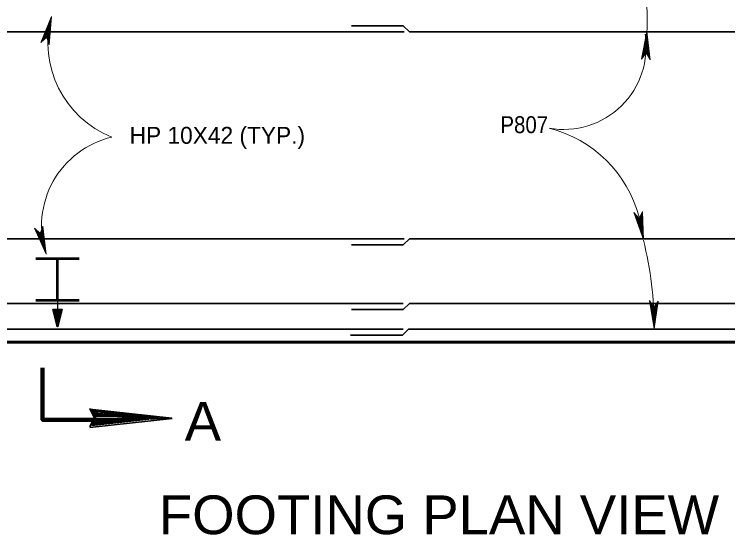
# Model space of a CAD drawing. Extents: x 144 to 252, y 360 to 425.
# Drawn here: x 160.77 to 174.56, y 388.73 to 398.8 of the extents above; entities that cross this region are included whole.
import ezdxf
from ezdxf.enums import TextEntityAlignment as Align

# ---------------------------------------------------------------- set-up
doc = ezdxf.new("R2010")
doc.units = 0
doc.header["$LTSCALE"] = 0.13
for name, color, linetype, lineweight in [('1', 7, 'Continuous', 40), ('10', 7, 'Continuous', 35), ('14', 7, 'Continuous', 13), ('16', 7, 'Continuous', 13), ('3', 7, 'Continuous', 13), ('9', 7, 'Continuous', 25)]:
    doc.layers.add(name, color=color, linetype=linetype, lineweight=lineweight)

msp = doc.modelspace()

# ---------------------------------------------------------------- linework, layer by layer
at = {"layer": '1', "lineweight": 35}
for p, q in [((156.5478, 398.4595), (168.3034, 398.4595)), ((168.4074, 398.4595), (180.0478, 398.4595)), ((156.5478, 394.4595), (168.3034, 394.4595)), ((168.4074, 394.4595), (180.0478, 394.4595)), ((156.5478, 393.2095), (168.2861, 393.2095)), ((168.4074, 393.2095), (180.0478, 393.2095)), ((156.5478, 392.7095), (168.2861, 392.7095)), ((168.3901, 392.7095), (180.0478, 392.7095)), ((162.2276, 391.1635), (163.8176, 390.9865)), ((162.2636, 391.1215), (163.4456, 390.9925)), ((162.2666, 391.1485), (163.4516, 391.0195)), ((162.2666, 391.1425), (163.4516, 391.0165)), ((162.2666, 391.1365), (163.4456, 391.0045)), ((162.2696, 391.1545), (163.4516, 391.0255)), ((163.8206, 390.9835), (162.2306, 390.8065)), ((162.2306, 390.9805), (163.8206, 390.9805)), ((162.2606, 390.8995), (163.3646, 391.0195)), ((162.2636, 390.8815), (163.3646, 391.0015)), ((162.2666, 390.8635), (163.3706, 390.9835)), ((162.2696, 390.8485), (163.3736, 390.9685))]:
    msp.add_line(p, q, dxfattribs=at)
at = {"layer": '1', "lineweight": 53}
for p, q in [((161.1876, 394.0775), (162.0272, 394.0775)), ((161.6073, 393.2692), (161.6073, 394.0775)), ((161.1875, 393.2692), (162.0271, 393.2692))]:
    msp.add_line(p, q, dxfattribs=at)
at = {"layer": '1', "lineweight": 25}
msp.add_line((161.6073, 393.2692), (161.6073, 392.7692), dxfattribs=at)
at = {"layer": '1', "lineweight": 60}
for p, q in [((180.2978, 392.4595), (156.2978, 392.4595)), ((156.2978, 392.4595), (180.2978, 392.4595))]:
    msp.add_line(p, q, dxfattribs=at)
msp.add_lwpolyline([(156.2978, 392.4595), (180.2978, 392.4595), (180.2978, 397.8819)], dxfattribs=at)
at = {"layer": '1', "lineweight": 35}
for points in [[(162.2336, 390.8215), (162.3176, 391.0015), (162.2336, 391.1755)], [(162.3416, 391.0195), (163.0496, 391.0285), (163.0466, 391.0105), (162.9086, 391.0195), (162.3416, 391.0285), (162.7976, 391.0435), (162.3206, 391.0525), (162.6566, 391.0645), (162.3086, 391.0825), (162.8516, 391.0405), (163.5596, 391.0105), (163.4126, 390.9715), (163.6076, 390.9895), (162.3416, 390.9835), (162.7106, 390.9595), (162.3206, 390.9595), (163.1306, 391.0165), (162.3146, 390.9265), (162.3446, 391.0165), (162.2786, 391.1275), (162.3146, 391.1035), (162.3446, 391.0405), (162.3866, 391.0585), (162.3596, 391.1095), (162.3356, 390.9955), (162.3026, 390.9265), (162.2696, 390.8485)]]:
    msp.add_lwpolyline(points, dxfattribs=at)
at = {"layer": '10'}
for p, q in [((161.6038, 392.9078), (161.6115, 393.0913)), ((161.6077, 393.0913), (161.6077, 392.7561)), ((161.6178, 393.0913), (161.6101, 392.9077)), ((161.6163, 392.9075), (161.6241, 393.0913)), ((161.6227, 392.9074), (161.6303, 393.0913)), ((161.6555, 393.0913), (161.6482, 392.9187))]:
    msp.add_line(p, q, dxfattribs=at)
for points in [[(161.5242, 393.0913), (161.6912, 393.0913), (161.6078, 392.7561)], [(161.5242, 393.0913), (161.6078, 392.7561), (161.5242, 393.0913)]]:
    msp.add_lwpolyline(points, dxfattribs=at)
msp.add_lwpolyline([(161.6078, 392.7561), (161.5242, 393.0913), (161.6912, 393.0913), (161.5242, 393.0913)], close=True, dxfattribs=at)
at = {"layer": '16', "lineweight": 106}
msp.add_lwpolyline([(161.3189, 391.9598), (161.3189, 390.9598), (162.3189, 390.9598)], dxfattribs=at)
at = {"layer": '16'}
for centre, radius, start, end in [((165.653, 398.6917), 7.3474, 358.12487, 8.06122), ((163.388, 398.2493), 1.9649, 164.92487, 248.20523), ((171.3847, 398.1691), 1.5968, 260.00291, 8.92656), ((170.5186, 394.2613), 2.4084, 15.03373, 75.84704), ((163.0645, 394.7075), 1.7647, 103.30356, 198.14467), ((166.5087, 392.7914), 6.6256, 359.34281, 14.34295)]:
    msp.add_arc(centre, radius, start, end, dxfattribs=at)
at = {"layer": '3'}
for p, q in [((161.4907, 398.7603), (161.2877, 398.2545)), ((161.4869, 398.7464), (161.2907, 398.2572)), ((161.4846, 398.7358), (161.2936, 398.2598)), ((161.4815, 398.7217), (161.2977, 398.2633)), ((161.4787, 398.7092), (161.301, 398.2664)), ((161.4762, 398.6982), (161.3041, 398.2692)), ((161.4732, 398.6842), (161.3082, 398.2727)), ((161.4704, 398.6717), (161.3116, 398.2757)), ((161.4675, 398.6583), (161.3153, 398.2791)), ((161.4012, 398.3547), (161.4907, 398.7603)), ((161.436, 398.2462), (161.4675, 398.6583)), ((161.4375, 398.2413), (161.4704, 398.6717)), ((161.439, 398.2368), (161.4732, 398.6842)), ((161.4406, 398.2317), (161.4762, 398.6982)), ((161.4419, 398.2278), (161.4787, 398.7092)), ((161.4419, 398.2278), (161.4787, 398.7092)), ((161.4434, 398.2233), (161.4815, 398.7217)), ((161.445, 398.2182), (161.4846, 398.7358)), ((161.4462, 398.2143), (161.4869, 398.7464)), ((161.4483, 398.2077), (161.4907, 398.7603)), ((161.4645, 398.6447), (161.3192, 398.2824)), ((161.4617, 398.6318), (161.3227, 398.2856)), ((161.4587, 398.6182), (161.3266, 398.2889)), ((161.4559, 398.6059), (161.33, 398.292)), ((161.4534, 398.5948), (161.3332, 398.2948)), ((161.4501, 398.5795), (161.3374, 398.2986)), ((161.4471, 398.566), (161.3413, 398.3019)), ((161.4427, 398.5485), (161.3452, 398.3054)), ((161.4398, 398.5349), (161.349, 398.3088)), ((161.4369, 398.5221), (161.3526, 398.312)), ((161.4354, 398.5131), (161.3561, 398.3151)), ((161.4191, 398.2987), (161.4354, 398.5131)), ((161.4196, 398.2971), (161.4369, 398.5221)), ((161.4212, 398.2924), (161.4398, 398.5349)), ((161.4227, 398.2875), (161.4427, 398.5485)), ((161.4239, 398.284), (161.4439, 398.5467)), ((161.4253, 398.2797), (161.4471, 398.566)), ((161.4269, 398.2747), (161.4501, 398.5795)), ((161.4286, 398.2692), (161.4534, 398.5948)), ((161.4299, 398.2651), (161.4559, 398.6059)), ((161.4313, 398.2607), (161.4587, 398.6182)), ((161.4329, 398.2557), (161.4617, 398.6318)), ((161.4344, 398.2511), (161.4645, 398.6447)), ((161.4328, 398.5014), (161.3593, 398.318)), ((161.4298, 398.4878), (161.3632, 398.3213)), ((161.4265, 398.4726), (161.3673, 398.3252)), ((161.4237, 398.4602), (161.3708, 398.3282)), ((161.4209, 398.4473), (161.3744, 398.3314)), ((161.4183, 398.4356), (161.3778, 398.3343)), ((161.4152, 398.4215), (161.3817, 398.3378)), ((161.4123, 398.4079), (161.3855, 398.3413)), ((161.4095, 398.3956), (161.3889, 398.3442)), ((161.4067, 398.3827), (161.3926, 398.3474)), ((161.4055, 398.3413), (161.4095, 398.3956)), ((161.4068, 398.3368), (161.4123, 398.4079)), ((161.4084, 398.332), (161.4152, 398.4215)), ((161.41, 398.3268), (161.4183, 398.4356)), ((161.4114, 398.3227), (161.4209, 398.4473)), ((161.4129, 398.3179), (161.4237, 398.4602)), ((161.4144, 398.3134), (161.4265, 398.4726)), ((161.4161, 398.3079), (161.4298, 398.4878)), ((161.4177, 398.3031), (161.4328, 398.5014)), ((172.9952, 398.4685), (172.8906, 397.9337)), ((172.994, 398.4541), (172.893, 397.9367)), ((172.9938, 398.4432), (172.8954, 397.9399)), ((172.9933, 398.4289), (172.8988, 397.9442)), ((172.9931, 398.4161), (172.9015, 397.9477)), ((172.9927, 398.4047), (172.904, 397.951)), ((172.9923, 398.3903), (172.9073, 397.9552)), ((172.9918, 398.3776), (172.9102, 397.9588)), ((172.9833, 398.0532), (172.9952, 398.4685)), ((173.0402, 397.9487), (172.9918, 398.3776)), ((173.0426, 397.9446), (172.9923, 398.3903)), ((173.0451, 397.9399), (172.9927, 398.4047)), ((173.0472, 397.9362), (172.9931, 398.4161)), ((173.0472, 397.9362), (172.9931, 398.4161)), ((173.0495, 397.932), (172.9933, 398.4289)), ((173.0519, 397.9274), (172.9938, 398.4432)), ((173.0539, 397.9238), (172.994, 398.4541)), ((173.0572, 397.9178), (172.9952, 398.4685)), ((161.2877, 398.2545), (161.4011, 398.3549)), ((161.4042, 398.3715), (161.3957, 398.3502)), ((161.402, 398.3616), (161.3985, 398.3527)), ((161.4011, 398.3549), (161.4483, 398.2077)), ((161.4026, 398.3501), (161.4042, 398.3715)), ((161.4036, 398.3472), (161.4055, 398.3724)), ((172.9915, 398.3639), (172.9132, 397.9628)), ((172.9912, 398.35), (172.9163, 397.9668)), ((172.9907, 398.3368), (172.9192, 397.9707)), ((172.9903, 398.3228), (172.9224, 397.9747)), ((172.9899, 398.3103), (172.9252, 397.9783)), ((172.9897, 398.299), (172.9278, 397.9817)), ((172.9892, 398.2833), (172.9312, 397.9862)), ((172.9888, 398.2694), (172.9343, 397.9902)), ((172.9878, 398.2514), (172.9375, 397.9943)), ((172.9874, 398.2375), (172.9406, 397.9984)), ((173.0146, 397.9958), (172.9874, 398.2375)), ((173.0171, 397.9913), (172.9878, 398.2514)), ((173.021, 397.984), (172.9888, 398.2694)), ((173.0236, 397.9796), (172.9892, 398.2833)), ((173.0188, 397.9882), (172.9893, 398.2498)), ((173.0263, 397.9744), (172.9897, 398.299)), ((173.0283, 397.9707), (172.9899, 398.3103)), ((173.0305, 397.9667), (172.9903, 398.3228)), ((173.0331, 397.9621), (172.9907, 398.3368)), ((173.0354, 397.9577), (172.9912, 398.35)), ((173.0379, 397.9532), (172.9915, 398.3639)), ((172.9871, 398.2243), (172.9436, 398.0022)), ((172.9872, 398.2152), (172.9464, 398.0058)), ((172.9869, 398.2032), (172.9491, 398.0093)), ((172.9864, 398.1894), (172.9522, 398.0134)), ((172.9861, 398.1737), (172.9557, 398.0179)), ((172.9857, 398.1612), (172.9584, 398.0215)), ((172.9853, 398.148), (172.9615, 398.0254)), ((172.985, 398.1359), (172.9642, 398.0288)), ((172.9846, 398.1215), (172.9673, 398.0331)), ((172.9842, 398.1077), (172.9704, 398.0371)), ((172.9922, 398.0368), (172.9842, 398.1077)), ((172.9947, 398.0323), (172.9846, 398.1215)), ((172.9973, 398.0276), (172.985, 398.1359)), ((172.9994, 398.0237), (172.9853, 398.148)), ((173.0017, 398.0193), (172.9857, 398.1612)), ((173.0041, 398.0152), (172.9861, 398.1737)), ((173.0067, 398.0102), (172.9864, 398.1894)), ((173.0093, 398.0057), (172.9869, 398.2032)), ((173.0122, 398.0001), (172.9871, 398.2243)), ((173.0114, 398.0016), (172.9872, 398.2152)), ((172.8906, 397.9337), (172.9832, 398.0535)), ((172.9837, 398.095), (172.9733, 398.0407)), ((172.9834, 398.0817), (172.9762, 398.0445)), ((172.9832, 398.0703), (172.9787, 398.0479)), ((172.9828, 398.0602), (172.9811, 398.0508)), ((172.9856, 398.049), (172.9832, 398.0703)), ((172.9832, 398.0535), (173.0572, 397.9178)), ((172.99, 398.0409), (172.9837, 398.095)), ((172.9872, 398.0463), (172.9843, 398.0714)), ((172.7463, 394.9668), (172.9281, 394.4433)), ((172.8486, 394.8508), (172.7463, 394.9668)), ((172.751, 394.9617), (172.926, 394.4576)), ((172.7536, 394.9587), (172.9239, 394.4682)), ((172.7572, 394.9547), (172.9212, 394.4823)), ((172.7603, 394.9511), (172.9187, 394.4948)), ((172.7603, 394.9511), (172.9187, 394.4948)), ((172.7631, 394.9479), (172.9165, 394.506)), ((172.7666, 394.944), (172.9137, 394.5202)), ((172.7697, 394.9404), (172.9113, 394.5327)), ((172.773, 394.9365), (172.9087, 394.5462)), ((172.7765, 394.9327), (172.906, 394.5598)), ((172.7798, 394.9291), (172.9035, 394.5727)), ((172.9124, 394.9881), (172.8486, 394.8508)), ((172.8932, 394.6252), (172.8844, 394.9278)), ((172.8962, 394.6099), (172.8868, 394.933)), ((172.8983, 394.5987), (172.8886, 394.9368)), ((172.9007, 394.5864), (172.8905, 394.941)), ((172.9035, 394.5727), (172.8926, 394.9456)), ((172.906, 394.5598), (172.8947, 394.95)), ((172.9087, 394.5462), (172.8968, 394.9546)), ((172.9113, 394.5327), (172.8989, 394.9592)), ((172.9137, 394.5202), (172.9008, 394.9633)), ((172.9165, 394.506), (172.9032, 394.9682)), ((172.9187, 394.4948), (172.9048, 394.9718)), ((172.9212, 394.4823), (172.9067, 394.9761)), ((172.9239, 394.4682), (172.9091, 394.9808)), ((172.926, 394.4576), (172.9108, 394.9844)), ((172.9281, 394.4433), (172.9124, 394.9881)), ((172.7832, 394.9251), (172.9007, 394.5864)), ((172.7862, 394.9216), (172.8983, 394.5987)), ((172.7891, 394.9183), (172.8962, 394.6099)), ((172.7928, 394.914), (172.8932, 394.6252)), ((172.7963, 394.9102), (172.8905, 394.6388)), ((172.7993, 394.9067), (172.8857, 394.6579)), ((172.8018, 394.904), (172.8875, 394.6567)), ((172.8052, 394.9001), (172.8848, 394.6703)), ((172.8084, 394.8964), (172.8823, 394.6832)), ((172.8095, 394.8951), (172.8801, 394.6921)), ((172.8125, 394.8917), (172.8778, 394.7038)), ((172.8159, 394.8879), (172.8751, 394.7174)), ((172.8197, 394.8835), (172.8722, 394.7328)), ((172.8229, 394.88), (172.8697, 394.7451)), ((172.8262, 394.8763), (172.8672, 394.7581)), ((172.829, 394.873), (172.8649, 394.7698)), ((172.8326, 394.8688), (172.8621, 394.7841)), ((172.836, 394.8651), (172.8595, 394.7978)), ((172.8391, 394.8615), (172.8569, 394.8102)), ((172.8431, 394.8569), (172.8514, 394.833)), ((172.8451, 394.8547), (172.8522, 394.8343)), ((172.8483, 394.851), (172.9281, 394.4433)), ((172.8502, 394.8443), (172.8499, 394.8539)), ((172.8522, 394.8343), (172.8516, 394.8572)), ((172.8545, 394.8232), (172.8533, 394.8611)), ((172.8569, 394.8102), (172.8554, 394.8654)), ((172.8595, 394.7978), (172.8573, 394.8696)), ((172.8621, 394.7841), (172.8595, 394.8742)), ((172.8649, 394.7698), (172.8617, 394.879)), ((172.8672, 394.7581), (172.8636, 394.883)), ((172.8697, 394.7451), (172.8656, 394.8874)), ((172.8722, 394.7328), (172.8676, 394.8915)), ((172.8751, 394.7174), (172.8699, 394.8967)), ((172.8778, 394.7038), (172.872, 394.9013)), ((172.8801, 394.6921), (172.8739, 394.9053)), ((172.8823, 394.6832), (172.8758, 394.9095)), ((172.8848, 394.6703), (172.8779, 394.9138)), ((172.8875, 394.6567), (172.88, 394.9185)), ((172.8905, 394.6388), (172.8822, 394.9233)), ((161.164, 394.6651), (161.3876, 394.158)), ((161.2752, 394.5577), (161.164, 394.6651)), ((161.169, 394.6603), (161.3843, 394.1721)), ((161.1718, 394.6575), (161.3814, 394.1825)), ((161.1757, 394.6538), (161.3775, 394.1963)), ((161.3277, 394.6997), (161.2752, 394.5577)), ((161.3525, 394.285), (161.3114, 394.6558)), ((161.3561, 394.2722), (161.3131, 394.6602)), ((161.3598, 394.2589), (161.3149, 394.665)), ((161.3636, 394.2457), (161.3166, 394.6697)), ((161.367, 394.2334), (161.3183, 394.6741)), ((161.3709, 394.2196), (161.3202, 394.6791)), ((161.374, 394.2087), (161.3216, 394.6829)), ((161.3775, 394.1963), (161.3231, 394.6873)), ((161.3814, 394.1825), (161.325, 394.6922)), ((161.3843, 394.1721), (161.3263, 394.696)), ((161.3876, 394.158), (161.3277, 394.6997)), ((161.1791, 394.6505), (161.374, 394.2087)), ((161.1791, 394.6505), (161.374, 394.2087)), ((161.1822, 394.6476), (161.3709, 394.2196)), ((161.186, 394.6438), (161.367, 394.2334)), ((161.1894, 394.6406), (161.3636, 394.2457)), ((161.193, 394.637), (161.3598, 394.2589)), ((161.1967, 394.6335), (161.3561, 394.2722)), ((161.2002, 394.6301), (161.3525, 394.285)), ((161.2041, 394.6264), (161.3487, 394.2984)), ((161.2073, 394.6232), (161.3453, 394.3105)), ((161.2105, 394.6202), (161.3423, 394.3215)), ((161.2146, 394.6162), (161.338, 394.3366)), ((161.2183, 394.6127), (161.3342, 394.3499)), ((161.2216, 394.6094), (161.3279, 394.3684)), ((161.2242, 394.6068), (161.3298, 394.3673)), ((161.228, 394.6033), (161.3261, 394.3807)), ((161.2315, 394.5999), (161.3225, 394.3934)), ((161.2327, 394.5987), (161.3196, 394.402)), ((161.2359, 394.5955), (161.3163, 394.4136)), ((161.2397, 394.592), (161.3126, 394.4269)), ((161.2438, 394.5879), (161.3083, 394.442)), ((161.2473, 394.5847), (161.3049, 394.4541)), ((161.2508, 394.5813), (161.3013, 394.4668)), ((161.254, 394.5782), (161.298, 394.4784)), ((161.2578, 394.5744), (161.2941, 394.4923)), ((161.2615, 394.5708), (161.2903, 394.5057)), ((161.2648, 394.5676), (161.2869, 394.5178)), ((161.2692, 394.5633), (161.2795, 394.5402)), ((161.2715, 394.5612), (161.2802, 394.5416)), ((161.275, 394.5578), (161.3876, 394.158)), ((161.2775, 394.5514), (161.2763, 394.5608)), ((161.2802, 394.5416), (161.2777, 394.5643)), ((161.2833, 394.5306), (161.2791, 394.5683)), ((161.2869, 394.5178), (161.2807, 394.5728)), ((161.2903, 394.5057), (161.2824, 394.5771)), ((161.2941, 394.4923), (161.2842, 394.5819)), ((161.298, 394.4784), (161.2859, 394.5868)), ((161.3013, 394.4668), (161.2875, 394.591)), ((161.3049, 394.4541), (161.2892, 394.5956)), ((161.3083, 394.442), (161.2908, 394.5998)), ((161.3126, 394.4269), (161.2927, 394.6052)), ((161.3163, 394.4136), (161.2945, 394.6099)), ((161.3196, 394.402), (161.296, 394.6141)), ((161.3225, 394.3934), (161.2977, 394.6184)), ((161.3261, 394.3807), (161.2993, 394.6229)), ((161.3298, 394.3673), (161.3011, 394.6277)), ((161.3342, 394.3499), (161.3029, 394.6327)), ((161.338, 394.3366), (161.3047, 394.6374)), ((161.3423, 394.3215), (161.3067, 394.6427)), ((161.3453, 394.3105), (161.3082, 394.6467)), ((161.3487, 394.2984), (161.3097, 394.651)), ((173.0482, 393.263), (173.1339, 392.7154)), ((173.128, 393.1305), (173.0482, 393.263)), ((173.0517, 393.257), (173.1343, 392.7298)), ((173.0538, 393.2536), (173.1342, 392.7407)), ((173.0565, 393.249), (173.134, 392.7551)), ((173.059, 393.245), (173.1338, 392.7678)), ((173.059, 393.245), (173.1338, 392.7678)), ((173.0612, 393.2413), (173.1337, 392.7792)), ((173.0639, 393.2367), (173.1334, 392.7936)), ((173.0664, 393.2328), (173.1333, 392.8063)), ((173.069, 393.2283), (173.1331, 392.8201)), ((173.0716, 393.224), (173.1328, 392.8339)), ((173.0742, 393.2197), (173.1327, 392.8472)), ((173.0769, 393.2153), (173.1324, 392.8611)), ((173.0793, 393.2113), (173.1322, 392.8737)), ((173.0815, 393.2076), (173.1321, 392.8851)), ((173.0844, 393.2027), (173.1318, 392.9007)), ((173.0872, 393.1982), (173.1317, 392.9146)), ((173.0895, 393.1943), (173.1303, 392.9342)), ((173.0914, 393.1912), (173.1319, 392.9326)), ((173.0941, 393.1868), (173.1317, 392.9465)), ((173.0967, 393.1826), (173.1315, 392.9597)), ((173.0975, 393.1811), (173.1308, 392.9688)), ((173.0998, 393.1773), (173.1307, 392.9808)), ((173.1026, 393.1728), (173.1305, 392.9946)), ((173.1054, 393.1679), (173.1302, 393.0102)), ((173.1079, 393.1638), (173.1301, 393.0228)), ((173.1105, 393.1596), (173.1299, 393.0361)), ((173.1128, 393.1558), (173.1297, 393.0481)), ((173.1155, 393.1512), (173.1295, 393.0626)), ((173.1182, 393.1468), (173.1293, 393.0764)), ((173.1206, 393.1427), (173.1291, 393.0891)), ((173.1238, 393.1376), (173.1277, 393.1125)), ((173.1253, 393.1349), (173.1287, 393.1137)), ((173.2152, 393.2543), (173.128, 393.1305)), ((173.1287, 393.1137), (173.1322, 393.1363)), ((173.1289, 393.1023), (173.1345, 393.1398)), ((173.1291, 393.0891), (173.1373, 393.1438)), ((173.1293, 393.0764), (173.14, 393.1475)), ((173.1295, 393.0626), (173.1429, 393.1517)), ((173.1297, 393.0481), (173.1459, 393.156)), ((173.1299, 393.0361), (173.1485, 393.1596)), ((173.1301, 393.0228), (173.1513, 393.1636)), ((173.1302, 393.0102), (173.154, 393.1672)), ((173.1305, 392.9946), (173.1572, 393.172)), ((173.1307, 392.9808), (173.1601, 393.1761)), ((173.1308, 392.9688), (173.1626, 393.1798)), ((173.1315, 392.9597), (173.1653, 393.1835)), ((173.1317, 392.9146), (173.1741, 393.1959)), ((173.1317, 392.9465), (173.1681, 393.1874)), ((173.1318, 392.9007), (173.177, 393.2)), ((173.1319, 392.9326), (173.171, 393.1916)), ((173.1321, 392.8851), (173.1803, 393.2047)), ((173.1322, 392.8737), (173.1827, 393.2081)), ((173.1324, 392.8611), (173.1853, 393.2119)), ((173.1327, 392.8472), (173.1882, 393.216)), ((173.1328, 392.8339), (173.191, 393.22)), ((173.1331, 392.8201), (173.194, 393.2241)), ((173.1333, 392.8063), (173.1968, 393.2283)), ((173.1334, 392.7936), (173.1995, 393.232)), ((173.1337, 392.7792), (173.2026, 393.2363)), ((173.1338, 392.7678), (173.205, 393.2397)), ((173.1339, 392.7154), (173.2152, 393.2543)), ((173.134, 392.7551), (173.2076, 393.2435)), ((173.1342, 392.7407), (173.2107, 393.2477)), ((173.1343, 392.7298), (173.213, 393.2511)), ((173.1278, 393.1307), (173.1339, 392.7154)), ((173.1286, 393.1239), (173.13, 393.1333))]:
    msp.add_line(p, q, dxfattribs=at)
at = {"layer": '3', "lineweight": 35}
for points in [[(168.4074, 398.4595), (168.2896, 398.5773), (167.2896, 398.5773)], [(168.4074, 394.4595), (168.2896, 394.3417), (167.2896, 394.3417)], [(168.4074, 393.2095), (168.2896, 393.0917), (167.2896, 393.0917)], [(168.3901, 392.7095), (168.2722, 392.5917), (167.2722, 392.5917)]]:
    msp.add_lwpolyline(points, dxfattribs=at)
at = {"layer": '9'}
for p, q in [((161.5289, 393.0725), (161.5298, 393.0913)), ((161.5343, 393.0509), (161.536, 393.0913)), ((161.5397, 393.0292), (161.5423, 393.0913)), ((161.5451, 393.0077), (161.5486, 393.0913)), ((161.5505, 392.9861), (161.5548, 393.0913)), ((161.5559, 392.9645), (161.5612, 393.0913)), ((161.5613, 392.9429), (161.5675, 393.0913)), ((161.5667, 392.9213), (161.5737, 393.0913)), ((161.5724, 392.9087), (161.58, 393.0913)), ((161.5787, 392.9085), (161.5863, 393.0913)), ((161.5849, 392.9083), (161.5927, 393.0913)), ((161.5913, 392.9082), (161.5989, 393.0913)), ((161.5975, 392.908), (161.6052, 393.0913)), ((161.6289, 392.9072), (161.6366, 393.0913)), ((161.6352, 392.9071), (161.6429, 393.0913)), ((161.6415, 392.9069), (161.6492, 393.0913)), ((161.6558, 392.9491), (161.6618, 393.0913)), ((161.6634, 392.9795), (161.6681, 393.0913)), ((161.6709, 393.0099), (161.6743, 393.0913)), ((161.6785, 393.0403), (161.6807, 393.0913)), ((161.6861, 393.0707), (161.6869, 393.0913)), ((161.5721, 392.8997), (161.5724, 392.9087)), ((161.5774, 392.8781), (161.5787, 392.9085)), ((161.5828, 392.8565), (161.5849, 392.9083)), ((161.5882, 392.8349), (161.5913, 392.9082)), ((161.5936, 392.8133), (161.5975, 392.908)), ((161.5989, 392.7917), (161.6038, 392.9078)), ((161.6043, 392.7701), (161.6101, 392.9077)), ((161.6105, 392.7668), (161.6163, 392.9075)), ((161.618, 392.7972), (161.6227, 392.9074)), ((161.6256, 392.8276), (161.6289, 392.9072)), ((161.6332, 392.8579), (161.6352, 392.9071)), ((161.6407, 392.8883), (161.6415, 392.9069))]:
    msp.add_line(p, q, dxfattribs=at)
at = {"layer": '9', "lineweight": 40}
msp.add_lwpolyline([(161.6078, 392.7561), (161.5242, 393.0913), (161.6912, 393.0913)], close=True, dxfattribs=at)

# ---------------------------------------------------------------- texts
at = {"layer": '14', "width": 1.05}
msp.add_text('FOOTING PLAN VIEW', height=0.75, dxfattribs=at).set_placement((168.979, 388.7452), align=Align.CENTER)
at = {"layer": '16', "width": 0.9}
msp.add_text('P807', height=0.3281, dxfattribs=at).set_placement((170.6267, 396.5012), align=Align.CENTER)
at = {"layer": '16'}
msp.add_text('HP 10X42 (TYP.)', height=0.3281, dxfattribs=at).set_placement((163.0018, 396.2952))
at = {"layer": '16', "width": 1.05}
msp.add_text('A', height=0.75, dxfattribs=at).set_placement((164.0666, 390.5544))

doc.saveas('drawing.dxf')
